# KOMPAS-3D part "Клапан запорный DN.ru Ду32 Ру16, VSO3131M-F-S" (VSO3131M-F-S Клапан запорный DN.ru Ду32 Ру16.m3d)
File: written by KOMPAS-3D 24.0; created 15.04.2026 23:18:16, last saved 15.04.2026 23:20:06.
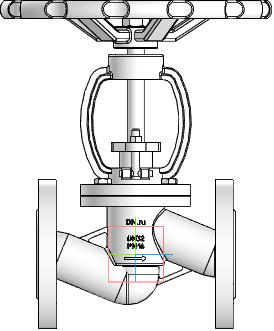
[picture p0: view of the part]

Document properties: Автор: R2D2; Полное имя файла: E:\Работа\Зайцев\VSO3131M-F-S Клапан запорный DN.ru Ду15-100 Ру16\DN32\VSO3131M-F-S Клапан запорный DN.ru Ду32 Ру16.m3d

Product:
- Part/product: Клапан запорный DN.ru Ду32 Ру16  | designation VSO3131M-F-S
    Масса: 7
    Раздел спецификации: Прочие изделия
    Примечание: D090-02949

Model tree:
1. Операция без истории:1

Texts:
  VSO3131M-F-S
